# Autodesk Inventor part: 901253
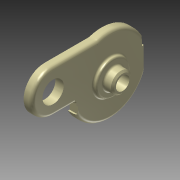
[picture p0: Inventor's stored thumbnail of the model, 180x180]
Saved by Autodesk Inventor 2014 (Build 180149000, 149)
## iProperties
Created: 2007-10
Part Number: 901253
Document SubType Name: Modeling
Designer: TH
Density: 1.13 g/cm^3
Mass: 11.4749 g
Surface Area: 58.4644 cm^2
Volume: 10.1548 cm^3
Material: Nylon Composite (Nylon, molybdenum disulphide)
Description: MOTOR SIDE MOUNT COVER
Appearance: Nylon 6
Component Category: Electrical
Author: TH
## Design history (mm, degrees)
node "900569" dims "d0" = 10
  sketch "Sketch1"
    geometry: L1 (-11.5, -6)-(-12.5, -5) reference; L2 (0, 0)-(0, -22.5) reference; L3 (0, -22.5)-(-3, -22.5) reference; L4 (-5, -20.5)-(-5, -11) reference; L5 (-6, -10)-(-6, -10) reference; L6 (-7, -9)-(-7, -7) reference; L7 (-8, -6)-(-11.5, -6) reference; L8 (-12.5, -5)-(-12.5, 0) reference; L9 (-12.5, 0)-(0, 0) reference; A1 r 2 centre (-3, -20.5) between (-5, -20.5) and (-3, -22.5) reference; A2 r 1 centre (-6, -11) between (-5, -11) and (-6, -10) reference; A3 r 1 centre (-6, -9) between (-7, -9) and (-6, -10) reference; A4 r 1 centre (-8, -7) between (-7, -7) and (-8, -6) reference; 4 further points
  sketch "Sketch2"
    geometry: L1 (20, -10.308)-(20, 10.308) reference; L2 (-20, 10.308)-(-20, -10.308) reference; L3 (0, 31.5)-(0, -31.5) reference; A1 r 22.5 centre (0, 0) between (-20, -10.308) and (20, 10.308) reference
  sketch "Sketch3"
    geometry: C1 r 5 at (0, 0) reference; C2 r 4 at (0, 0) reference
  sketch "Sketch4"
    geometry: L1 (-20, 10.308)-(-20, 5.938) reference; L2 (20, -5.938)-(20, -10.308) reference; L3 (20, -10.308)-(18.995, -10.308) reference; L4 (18.995, -10.308)-(18.995, -5.938) reference; L5 (18.995, -5.938)-(20, -5.938) reference; L6 (-18.995, 10.308)-(-20, 10.308) reference; L7 (-20, 5.938)-(-18.995, 5.938) reference; L8 (-18.995, 5.938)-(-18.995, 10.308) reference; L9 (20, 10.308)-(20, -10.308) reference; L10 (-20, -10.308)-(-20, 10.308) reference
  sketch "Sketch5"
    geometry: L1 (-18.995, 5.938)-(-18.995, 10.308) reference; L2 (20, -3.777)-(33.813, -3.777) reference; L3 (46.313, 8.723)-(46.313, 8.723) reference; L4 (33.813, 21.223)-(7.471, 21.223) reference; L5 (-20, 5.938)-(-18.995, 5.938) reference; L6 (20, -3.777)-(15, -3.777) reference; L7 (15, -3.777)-(15, 0) reference; L8 (7.471, 21.223)-(4.981, 14.149) reference; L9 (20, 10.308)-(20, -5.938) reference; C1 r 6.33 at (33.813, 8.723) reference; C2 r 4 at (0, 0) reference; A1 r 12.5 centre (33.813, 8.723) between (33.813, -3.777) and (46.313, 8.723) reference; A2 r 12.5 centre (33.813, 8.723) between (46.313, 8.723) and (33.813, 21.223) reference; A3 r 15 centre (0, 0) between (15, 0) and (4.981, 14.149) reference; 1 further point
  sketch "Sketch6"
    geometry: L1 (42.024, 7.924)-(45.013, 7.663) reference; L2 (35.405, 0.629)-(35.926, -2.326) reference; L3 (42.024, 9.523)-(45.013, 9.784) reference; L4 (35.405, 16.818)-(35.926, 19.773) reference; L5 (20, -4.777)-(20, -5.938) reference; L6 (20, -5.938)-(18.995, -5.938) reference; L7 (-18.995, 10.308)-(-20, 10.308) reference; L8 (33.813, 8.723)-(33.813, -2.527) reference; L9 (33.813, -2.527)-(21.313, -2.527) reference; L10 (33.813, 0.473)-(21.313, 0.473) reference; L11 (21.313, -2.527)-(21.313, 0.473) reference; L12 (33.813, 8.723)-(33.813, 16.973) reference; L13 (33.813, 16.973)-(15.813, 16.973) reference; L14 (15.813, 16.973)-(15.813, 19.973) reference; L15 (33.813, 19.973)-(15.813, 19.973) reference; L16 (33.813, 16.973)-(33.813, 19.973) reference; C1 r 6.33 at (33.813, 8.723) reference; A1 r 8.25 centre (33.813, 8.723) between (42.024, 9.523) and (35.405, 16.818) reference; A2 r 8.25 centre (33.813, 8.723) between (35.405, 0.629) and (42.024, 7.924) reference; A3 r 11.25 centre (33.813, 8.723) between (45.013, 9.784) and (35.926, 19.773) reference; A4 r 11.25 centre (33.813, 8.723) between (35.926, -2.326) and (45.013, 7.663) reference; A5 r 12.5 centre (33.813, 8.723) between (33.813, -3.777) and (33.813, 21.223) reference
body "Solid1"
tag "TaggingFeature2"
feature "DerivedBody::D-900569" dims "d0" = 10
